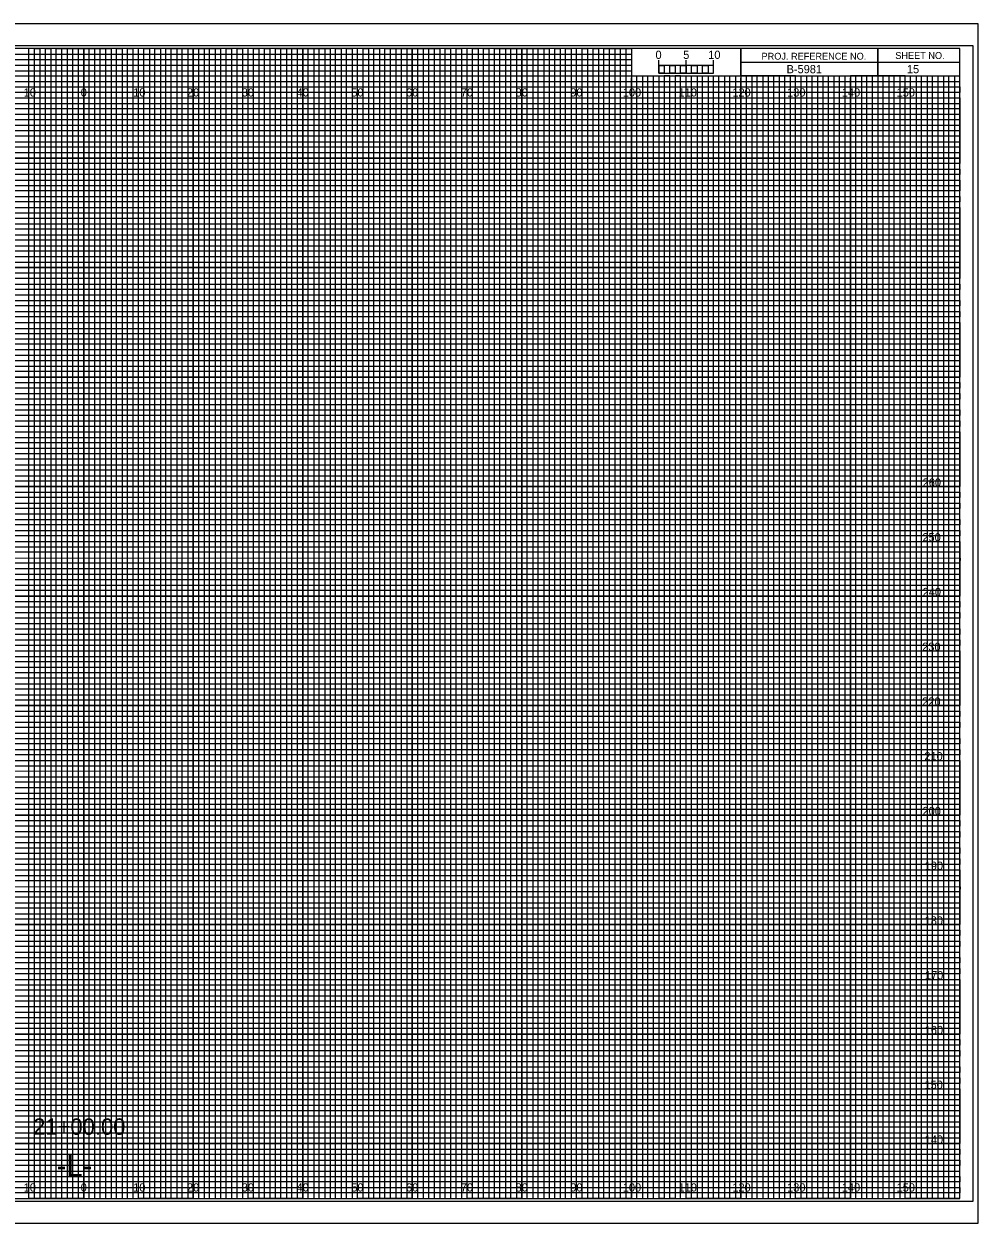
# Model space of a CAD drawing. Extents: x -13 to 323, y -5 to 4174.
# Drawn here: x 149.1 to 323.3, y 1975.5 to 2194.5 of the extents above; entities that cross this region are included whole.
import ezdxf

# ---------------------------------------------------------------- set-up
doc = ezdxf.new("R2010")
doc.units = 0
for name, color, linetype in [('Exist Cross Section Cell', 7, 'Continuous'), ('Exist XS Center Line Elevation Label', 7, 'Continuous'), ('Exist XS Ground Line', 7, 'Continuous'), ('Prop CMT Concrete Structures', 7, 'Continuous'), ('Prop CMT Guardrail Graphics', 7, 'Continuous'), ('Prop CMT Pvmt Course 1', 7, 'Continuous'), ('Prop CMT Pvmt Course 2', 7, 'Continuous'), ('Prop CMT Pvmt Course 3', 7, 'Continuous'), ('Prop CMT Pvmt Surface', 7, 'Continuous'), ('Prop CMT Shld Paved Course 1', 7, 'Continuous'), ('Prop CMT Shld Paved Course 2', 7, 'Continuous'), ('Prop CMT Shld Paved Course 3', 7, 'Continuous'), ('Prop CMT Subgrade Earthwork', 7, 'Continuous'), ('Prop XS Ditch Standard Text', 7, 'Continuous'), ('Prop XS SE Text', 7, 'Continuous'), ('Prop XS Side Slope Text', 7, 'Continuous'), ('Scratch_Level_0', 7, 'Continuous')]:
    doc.layers.add(name, color=color, linetype=linetype)

msp = doc.modelspace()

# ---------------------------------------------------------------- linework, layer by layer
at = {"layer": 'Exist XS Center Line Elevation Label'}
for points in [[(145, 1980), (155, 1980), (155, 2190), (165, 2190), (165, 1980), (175, 1980), (175, 2190), (185, 2190), (185, 1980), (195, 1980), (195, 2190), (205, 2190), (205, 1980), (215, 1980), (215, 2190), (225, 2190), (225, 1980), (235, 1980), (235, 2190), (245, 2190), (245, 1980), (255, 1980), (255, 2190), (259.93, 2190), (260, 2190), (260, 2185), (264.99, 2185), (264.99, 1980), (275, 1980), (275, 2185), (285, 2185), (285, 1980), (295, 1980), (295, 2185), (305, 2185), (305, 1980), (315, 1980), (315, 2185)], [(0, 2185), (275, 2185)], [(0, 2165), (320, 2165), (320, 2175), (0, 2175)], [(0, 2145), (320, 2145), (320, 2155), (0, 2155)], [(0, 2125), (320, 2125), (320, 2135), (0, 2135)], [(0, 2105), (320, 2105), (320, 2115), (0, 2115)], [(0, 2085), (320, 2085), (320, 2095), (0, 2095)], [(0, 2065), (320, 2065), (320, 2075), (0, 2075)], [(0, 2045), (320, 2045), (320, 2055), (0, 2055)], [(0, 2025), (320, 2025), (320, 2035), (0, 2035)], [(0, 2005), (320, 2005), (320, 2015), (0, 2015)], [(0, 1985), (320, 1985), (320, 1995), (0, 1995)]]:
    msp.add_lwpolyline(points, dxfattribs=at)
at = {"layer": 'Exist XS Ground Line'}
for p, q in [((150, 2190), (140, 2190)), ((150, 1980), (150, 2190)), ((170, 2190), (160, 2190)), ((160, 2190), (160, 1980)), ((170, 1980), (170, 2190)), ((190, 2190), (180, 2190)), ((180, 2190), (180, 1980)), ((190, 1980), (190, 2190)), ((210, 2190), (200, 2190)), ((200, 2190), (200, 1980)), ((210, 1980), (210, 2190)), ((230, 2190), (220, 2190)), ((220, 2190), (220, 1980)), ((230, 1980), (230, 2190)), ((250, 2190), (240, 2190)), ((240, 2190), (240, 1980)), ((250, 1980), (250, 2190)), ((260, 2190), (260, 1980)), ((270, 1980), (270, 2185)), ((290, 2185), (280, 2185)), ((280, 2185), (280, 1980)), ((290, 1980), (290, 2185)), ((310, 2185), (300, 2185)), ((300, 2185), (300, 1980)), ((310, 1980), (310, 2185)), ((160, 1980), (150, 1980)), ((180, 1980), (170, 1980)), ((200, 1980), (190, 1980)), ((220, 1980), (210, 1980)), ((240, 1980), (230, 1980)), ((260, 1980), (250, 1980)), ((280, 1980), (270, 1980)), ((300, 1980), (290, 1980)), ((320, 1980), (310, 1980)), ((320, 1980), (320, 1980))]:
    msp.add_line(p, q, dxfattribs=at)
for points in [[(0, 2180), (320, 2180), (320, 2170), (0, 2170)], [(0, 2160), (320, 2160), (320, 2150), (0, 2150)], [(0, 2140), (320, 2140), (320, 2130), (0, 2130)], [(0, 2120), (320, 2120), (320, 2110), (0, 2110)], [(0, 2100), (320, 2100), (320, 2090), (0, 2090)], [(0, 2080), (320, 2080), (320, 2070), (0, 2070)], [(0, 2060), (320, 2060), (320, 2050), (0, 2050)], [(0, 2040), (320, 2040), (320, 2030), (0, 2030)], [(0, 2020), (320, 2020), (320, 2010), (0, 2010)], [(0, 2000), (320, 2000), (320, 1990), (0, 1990)]]:
    msp.add_lwpolyline(points, dxfattribs=at)
at = {"layer": 'Prop CMT Pvmt Course 1'}
for p, q in [((323.3, 2194.5), (-13.4, 2194.5)), ((-13.4, 1975.5), (323.3, 1975.5))]:
    msp.add_line(p, q, dxfattribs=at)
at = {"layer": 'Prop CMT Pvmt Course 2'}
msp.add_lwpolyline([(-13.4, 1975.5), (323.3, 1975.5), (323.3, 2194.5), (-13.4, 2194.5)], close=True, dxfattribs=at)
at = {"layer": 'Prop CMT Pvmt Course 3'}
msp.add_lwpolyline([(-10.8, 1979.5), (322.4, 1979.5), (322.4, 2190.5), (-10.8, 2190.5)], close=True, dxfattribs=at)
at = {"layer": 'Prop CMT Shld Paved Course 1'}
for p, q in [((305, 2190), (305, 2185)), ((305, 2185), (305, 2190)), ((280, 2187.5), (280, 2185)), ((320, 2187.49), (280, 2187.49)), ((280, 2185), (320, 2185))]:
    msp.add_line(p, q, dxfattribs=at)
for points in [[(320, 2190), (0, 2190), (0, 1980), (320, 1980)], [(280, 2190), (260, 2190), (260, 2185.03), (280, 2185.03)], [(320, 2190), (280, 2190), (280, 2185), (320, 2185)]]:
    msp.add_lwpolyline(points, close=True, dxfattribs=at)
at = {"layer": 'Prop CMT Shld Paved Course 2'}
for p, q in [((267, 2185), (266.01, 2185)), ((266.01, 2185), (266.01, 1980)), ((267, 1980), (267, 2185)), ((269, 2185), (268, 2185)), ((268, 2185), (268, 1980)), ((269, 1980), (269, 2185)), ((266.01, 1980), (265, 1980)), ((268, 1980), (267, 1980))]:
    msp.add_line(p, q, dxfattribs=at)
for points in [[(150, 1980), (151, 1980), (151, 2190), (152, 2190), (152, 1980)], [(152, 1980), (153, 1980), (153, 2190), (154, 2190), (154, 1980)], [(155, 1980), (156, 1980), (156, 2190), (157, 2190), (157, 1980)], [(157, 1980), (158, 1980), (158, 2190), (159, 2190), (159, 1980)], [(160, 1980), (161, 1980), (161, 2190), (162, 2190), (162, 1980)], [(162, 1980), (163, 1980), (163, 2190), (164, 2190), (164, 1980)], [(165, 1980), (166, 1980), (166, 2190), (167, 2190), (167, 1980)], [(167, 1980), (168, 1980), (168, 2190), (169, 2190), (169, 1980)], [(170, 1980), (171, 1980), (171, 2190), (172, 2190), (172, 1980)], [(172, 1980), (173, 1980), (173, 2190), (174, 2190), (174, 1980)], [(175, 1980), (176, 1980), (176, 2190), (177, 2190), (177, 1980)], [(177, 1980), (178, 1980), (178, 2190), (179, 2190), (179, 1980)], [(180, 1980), (181, 1980), (181, 2190), (182, 2190), (182, 1980)], [(182, 1980), (183, 1980), (183, 2190), (184, 2190), (184, 1980)], [(185, 1980), (186, 1980), (186, 2190), (187, 2190), (187, 1980)], [(187, 1980), (188, 1980), (188, 2190), (189, 2190), (189, 1980)], [(190, 1980), (191, 1980), (191, 2190), (192, 2190), (192, 1980)], [(192, 1980), (193, 1980), (193, 2190), (194, 2190), (194, 1980)], [(195, 1980), (196, 1980), (196, 2190), (197, 2190), (197, 1980)], [(197, 1980), (198, 1980), (198, 2190), (199, 2190), (199, 1980)], [(200, 1980), (201, 1980), (201, 2190), (202, 2190), (202, 1980)], [(202, 1980), (203, 1980), (203, 2190), (204, 2190), (204, 1980)], [(205, 1980), (206, 1980), (206, 2190), (207, 2190), (207, 1980)], [(207, 1980), (208, 1980), (208, 2190), (209, 2190), (209, 1980)], [(210, 1980), (211, 1980), (211, 2190), (212, 2190), (212, 1980)], [(212, 1980), (213, 1980), (213, 2190), (214, 2190), (214, 1980)], [(215, 1980), (216, 1980), (216, 2190), (217, 2190), (217, 1980)], [(217, 1980), (218, 1980), (218, 2190), (219, 2190), (219, 1980)], [(220, 1980), (221, 1980), (221, 2190), (222, 2190), (222, 1980)], [(222, 1980), (223, 1980), (223, 2190), (224, 2190), (224, 1980)], [(225, 1980), (226, 1980), (226, 2190), (227, 2190), (227, 1980)], [(227, 1980), (228, 1980), (228, 2190), (229, 2190), (229, 1980)], [(230, 1980), (231, 1980), (231, 2190), (232, 2190), (232, 1980)], [(232, 1980), (233, 1980), (233, 2190), (234, 2190), (234, 1980)], [(235, 1980), (236, 1980), (236, 2190), (237, 2190), (237, 1980)], [(237, 1980), (238, 1980), (238, 2190), (239, 2190), (239, 1980)], [(240, 1980), (241, 1980), (241, 2190), (242, 2190), (242, 1980)], [(242, 1980), (243, 1980), (243, 2190), (244, 2190), (244, 1980)], [(245, 1980), (246, 1980), (246, 2190), (247, 2190), (247, 1980)], [(247, 1980), (248, 1980), (248, 2190), (249, 2190), (249, 1980)], [(250, 1980), (251, 1980), (251, 2190), (252, 2190), (252, 1980)], [(252, 1980), (253, 1980), (253, 2190), (254, 2190), (254, 1980)], [(255, 1980), (256, 1980), (256, 2190), (257, 2190), (257, 1980)], [(257, 1980), (258, 1980), (258, 2190), (259, 2190), (259, 1980)], [(260, 1980), (261, 1980), (261, 2185), (262.02, 2185), (262.02, 1980)], [(262, 1980), (263, 1980), (263, 2185), (263.99, 2185), (263.99, 1980)], [(270, 1980), (270.98, 1980), (270.98, 2185), (272, 2185), (272, 1980)], [(272, 1980), (273, 1980), (273, 2185), (274.05, 2185), (274.05, 1980)], [(275, 1980), (276, 1980), (276, 2185), (277, 2185), (277, 1980)], [(277, 1980), (278, 1980), (278, 2185), (279, 2185), (279, 1980)], [(280, 1980), (281, 1980), (281, 2185), (282, 2185), (282, 1980)], [(282, 1980), (283, 1980), (283, 2185), (284, 2185), (284, 1980)], [(285, 1980), (286, 1980), (286, 2185), (287, 2185), (287, 1980)], [(287, 1980), (288, 1980), (288, 2185), (289, 2185), (289, 1980)], [(290, 1980), (291, 1980), (291, 2185), (292, 2185), (292, 1980)], [(292, 1980), (293, 1980), (293, 2185), (294, 2185), (294, 1980)], [(295, 1980), (296, 1980), (296, 2185), (297, 2185), (297, 1980)], [(297, 1980), (298, 1980), (298, 2185), (299, 2185), (299, 1980)], [(300, 1980), (301, 1980), (301, 2185), (302, 2185), (302, 1980)], [(302, 1980), (303, 1980), (303, 2185), (304, 2185), (304, 1980)], [(305, 1980), (306, 1980), (306, 2185), (307, 2185), (307, 1980)], [(307, 1980), (308, 1980), (308, 2185), (309, 2185), (309, 1980)], [(310, 1980), (311, 1980), (311, 2185), (312, 2185), (312, 1980)], [(312, 1980), (313, 1980), (313, 2185), (314, 2185), (314, 1980)], [(315, 1980), (316, 1980), (316, 2185), (317, 2185), (317, 1980)], [(317, 1980), (318, 1980), (318, 2185), (319, 2185), (319, 1980)]]:
    msp.add_lwpolyline(points, dxfattribs=at)
at = {"layer": 'Prop CMT Shld Paved Course 3'}
for p, q in [((265, 2185.49), (265, 2187.9)), ((265, 2186.9), (265, 2187.9)), ((270, 2185.49), (270, 2187.9)), ((275, 2185.49), (275, 2187.9)), ((275, 2186.9), (275, 2187.9))]:
    msp.add_line(p, q, dxfattribs=at)
for points in [[(275, 2186.9), (265, 2186.9), (265, 2185.49), (275, 2185.49)], [(265, 2186.9), (266, 2186.9), (266, 2185.49), (265, 2185.49)], [(267, 2186.9), (268, 2186.9), (268, 2185.49), (267, 2185.49)], [(269, 2186.9), (270, 2186.9), (270, 2185.49), (269, 2185.49)], [(271, 2186.9), (272, 2186.9), (272, 2185.49), (271, 2185.49)], [(273, 2186.9), (274, 2186.9), (274, 2185.49), (273, 2185.49)]]:
    msp.add_lwpolyline(points, close=True, dxfattribs=at)
at = {"layer": 'Prop CMT Subgrade Earthwork'}
for p, q in [((150, 1980), (150, 2190)), ((160, 1980), (160, 2190)), ((170, 1980), (170, 2190)), ((180, 1980), (180, 2190)), ((190, 1980), (190, 2190)), ((200, 1980), (200, 2190)), ((210, 1980), (210, 2190)), ((220, 1980), (220, 2190)), ((230, 1980), (230, 2190)), ((240, 1980), (240, 2190)), ((250, 1980), (250, 2190)), ((260, 1980), (260, 2184.69)), ((270, 1980), (270, 2184.69)), ((280, 1980), (280, 2184.69)), ((290, 1980), (290, 2184.69)), ((300, 1980), (300, 2184.69)), ((310, 1980), (310, 2184.69)), ((0, 2180), (320, 2180)), ((0, 2170), (320, 2170)), ((0, 2160), (320, 2160)), ((0, 2150), (320, 2150)), ((0, 2140), (320, 2140)), ((0, 2130), (320, 2130)), ((0, 2120), (320, 2120)), ((0, 2110), (320, 2110)), ((0, 2100), (320, 2100)), ((0, 2090), (320, 2090)), ((0, 2080), (320, 2080)), ((0, 2070), (320, 2070)), ((0, 2060), (320, 2060)), ((0, 2050), (320, 2050)), ((0, 2040), (320, 2040)), ((0, 2030), (320, 2030)), ((0, 2020), (320, 2020)), ((0, 2010), (320, 2010)), ((0, 2000), (320, 2000)), ((0, 1990), (320, 1990))]:
    msp.add_line(p, q, dxfattribs=at)
at = {"layer": 'Scratch_Level_0'}
for p, q in [((0, 2189), (260, 2189)), ((260, 2187.98), (0, 2187.98)), ((260, 2189), (260, 2187.98)), ((0, 2187), (260, 2187)), ((260, 2185.89), (0, 2185.89)), ((260, 2187), (260, 2185.89)), ((0, 2184), (320, 2184))]:
    msp.add_line(p, q, dxfattribs=at)
for points in [[(0, 2183), (270, 2183), (320, 2183), (320, 2182), (0, 2182)], [(0, 2181), (320, 2181), (320, 2179), (0, 2179)], [(0, 2178), (320, 2178), (320, 2177), (0, 2176.98)], [(0, 2176), (320, 2176), (320, 2174), (0, 2174)], [(0, 2173), (320, 2173), (320, 2172), (0, 2172)], [(0, 2171), (320, 2171), (320, 2169), (0, 2169)], [(0, 2168), (320, 2168), (320, 2167), (0, 2167)], [(0, 2166), (320, 2166), (320, 2164), (0, 2164)], [(0, 2163), (320, 2163), (320, 2162), (0, 2162)], [(0, 2161), (320, 2161), (320, 2159), (0, 2159)], [(0, 2158), (320, 2158), (320, 2157), (0, 2157)], [(0, 2156), (320, 2156), (320, 2153.95), (320, 2153), (320, 2152), (0, 2152)], [(0, 2154), (320, 2154), (320, 2153), (0, 2153)], [(0, 2151), (320, 2151), (320, 2149), (0, 2149.03)], [(0, 2149.03), (320, 2149), (320, 2148), (0, 2148)], [(0, 2147), (320, 2147), (320, 2146), (0, 2146)], [(0, 2144), (320, 2144), (320, 2143), (0, 2143)], [(0, 2142), (320, 2142), (320, 2141), (0, 2141)], [(-0.07, 2138.89), (320, 2138.89), (320, 2137.88), (-0.07, 2137.88)], [(0, 2137), (320, 2137), (320, 2136), (0, 2136)], [(0, 2134), (320, 2134), (320, 2133), (0, 2133)], [(0, 2132), (320, 2132), (320, 2131), (0, 2131)], [(0, 2129), (320, 2129), (320, 2128), (0, 2128)], [(0, 2127), (320, 2127), (320, 2126), (0, 2126)], [(0, 2124), (320, 2124), (320, 2123), (0, 2123)], [(0, 2122), (320, 2122), (320, 2121), (0, 2121)], [(0, 2119), (320, 2119), (319.99, 2117.98), (0, 2118)], [(0, 2117), (320, 2117), (320, 2116), (0, 2116)], [(0, 2114), (320, 2114), (320, 2113), (0, 2113)], [(0, 2112), (320, 2112), (320, 2111), (0, 2111)], [(0, 2109), (320, 2109), (320, 2108), (0, 2108)], [(0, 2107), (320, 2107), (320, 2106), (0, 2106)], [(0, 2104), (320, 2104), (320, 2103), (0, 2103)], [(0, 2102), (320, 2102), (320, 2101), (0, 2101)], [(0, 2099), (320, 2099), (320, 2098), (0, 2098)], [(0, 2096.99), (320.07, 2096.91), (320, 2096), (0, 2096)], [(0, 2094), (320, 2094), (320, 2093), (0, 2093)], [(0, 2092), (320, 2092), (320, 2091), (0, 2091)], [(0, 2089), (320, 2089), (320, 2088), (0, 2088)], [(0, 2087), (320, 2087), (320, 2086), (0, 2086)], [(0, 2084), (320, 2084), (320, 2083), (0, 2083)], [(0, 2082), (320, 2082), (320, 2081), (0, 2081)], [(0, 2079), (320, 2079), (320, 2078), (0, 2078)], [(0, 2077), (320, 2077), (320, 2076), (0, 2076)], [(0, 2074), (320, 2074), (320, 2073), (0, 2073)], [(0, 2072), (320, 2072), (320, 2071), (0, 2071)], [(0, 2069), (320, 2069), (320, 2068), (0, 2068)], [(0, 2067), (320, 2067), (320, 2066), (0, 2066)], [(0, 2064), (320, 2064), (320, 2063), (0, 2063)], [(0, 2062), (320, 2062), (320, 2061), (0, 2061)], [(0, 2059), (320, 2059), (319.99, 2057.98), (0, 2058)], [(0, 2057), (320, 2057), (320, 2056), (0, 2056)], [(0, 2054), (320, 2054), (320, 2053), (0, 2053)], [(0, 2052), (320, 2052), (320, 2051), (0, 2051)], [(0, 2049), (320, 2049), (320, 2048), (0, 2048)], [(0, 2047), (320, 2047), (320, 2046), (0, 2046)], [(0, 2044), (320, 2044), (320, 2043), (0, 2043)], [(0, 2042), (320, 2042), (320, 2041), (0, 2041)], [(0, 2039), (320, 2039), (320, 2038), (0, 2038)], [(0, 2036.99), (320.07, 2036.91), (320, 2036), (0, 2036)], [(0, 2034), (320, 2034), (320, 2033), (0, 2033)], [(0, 2032), (320, 2032), (320, 2031), (0, 2031)], [(0, 2029), (320, 2029), (320, 2028), (0, 2028)], [(0, 2027), (320, 2027), (320, 2026), (0, 2026)], [(0, 2024), (320, 2024), (320, 2023), (0, 2023)], [(0, 2022), (320, 2022), (320, 2021), (0, 2021)], [(0, 2019), (320, 2019), (320, 2018), (0, 2018)], [(0, 2017), (320, 2017), (320, 2016), (0, 2016)], [(0, 2014), (320, 2014), (320, 2013), (0, 2013)], [(0, 2012), (320, 2012), (320, 2011), (0, 2011)], [(0, 2009), (320, 2009), (320, 2008), (0, 2008)], [(0, 2007), (320, 2007), (320, 2006), (0, 2006)], [(0, 2004), (320, 2004), (320, 2003), (0, 2003)], [(0, 2002), (320, 2002), (320, 2001), (0, 2001)], [(0, 1999), (320, 1999), (320, 1998), (0, 1998)], [(0, 1997), (320, 1997), (320, 1996), (0, 1996)], [(0, 1994), (320, 1994), (320, 1993), (0, 1993)], [(0, 1992), (320, 1992), (320, 1991), (0, 1991)], [(0, 1989), (320, 1989), (320, 1988), (0, 1988)], [(0, 1987), (320, 1987), (320, 1986), (0, 1986)], [(0, 1984), (320, 1984), (320, 1983), (0, 1983)], [(0, 1982), (320, 1982), (320, 1981), (0, 1981)]]:
    msp.add_lwpolyline(points, dxfattribs=at)

# ---------------------------------------------------------------- texts
at = {"layer": 'Exist Cross Section Cell'}
for s, p in [('10', (149.04, 2181.25)), ('0', (159.45, 2181.25)), ('0', (159.45, 2181.25)), ('10', (169.04, 2181.25)), ('20', (178.86, 2181.25)), ('30', (188.86, 2181.25)), ('40', (198.86, 2181.25)), ('50', (208.86, 2181.25)), ('60', (218.86, 2181.25)), ('70', (228.86, 2181.25)), ('80', (238.86, 2181.25)), ('90', (248.86, 2181.25)), ('100', (258.44, 2181.25)), ('110', (268.62, 2181.25)), ('120', (278.44, 2181.25)), ('130', (288.44, 2181.25)), ('140', (298.44, 2181.25)), ('150', (308.44, 2181.25)), ('10', (149.04, 1981.25)), ('0', (159.45, 1981.25)), ('0', (159.45, 1981.25)), ('10', (169.04, 1981.25)), ('20', (178.86, 1981.25)), ('30', (188.86, 1981.25)), ('40', (198.86, 1981.25)), ('50', (208.86, 1981.25)), ('60', (218.86, 1981.25)), ('70', (228.86, 1981.25)), ('80', (238.86, 1981.25)), ('90', (248.86, 1981.25)), ('100', (258.44, 1981.25)), ('110', (268.62, 1981.25)), ('120', (278.44, 1981.25)), ('130', (288.44, 1981.25)), ('140', (298.44, 1981.25)), ('150', (308.44, 1981.25))]:
    msp.add_text(s, height=1.5, dxfattribs=at).set_placement(p)
at = {"layer": 'Prop CMT Concrete Structures'}
msp.add_text('21+00.00', height=3, dxfattribs=at).set_placement((150.77, 1991.61))
at = {"layer": 'Prop CMT Guardrail Graphics'}
for s, p in [('260', (313.19, 2110)), ('250', (313.15, 2100)), ('240', (313.19, 2090)), ('230', (313.11, 2080)), ('220', (313.12, 2070)), ('210', (313.5, 2060)), ('200', (313.17, 2050)), ('190', (313.57, 2040)), ('180', (313.55, 2030)), ('170', (313.61, 2020)), ('160', (313.57, 2010)), ('150', (313.52, 2000)), ('140', (313.57, 1990))]:
    msp.add_text(s, height=1.5, dxfattribs=at).set_placement(p)
at = {"layer": 'Prop CMT Pvmt Surface'}
for s, p in [('5', (269.47, 2188.12)), ('10', (274.04, 2188.12))]:
    msp.add_text(s, height=1.5, dxfattribs=at).set_placement(p)
at = {"layer": 'Prop CMT Shld Paved Course 1'}
for s, p in [('PROJ. REFERENCE NO.', (283.77, 2187.99)), ('SHEET NO.', (308.19, 2188.12))]:
    msp.add_text(s, height=1.25, dxfattribs=at).set_placement(p)
at = {"layer": 'Prop CMT Shld Paved Course 3'}
msp.add_text('0', height=1.5, dxfattribs=at).set_placement((264.41, 2188.12))
at = {"layer": 'Prop XS Ditch Standard Text'}
msp.add_text('-L-', height=4, dxfattribs=at).set_placement((155.06, 1984))
at = {"layer": 'Prop XS SE Text'}
msp.add_text(' B-5981', height=1.5, dxfattribs=at).set_placement((287.79, 2185.5))
at = {"layer": 'Prop XS Side Slope Text'}
msp.add_text('15', height=1.5, dxfattribs=at).set_placement((310.32, 2185.5))

doc.saveas('drawing.dxf')
